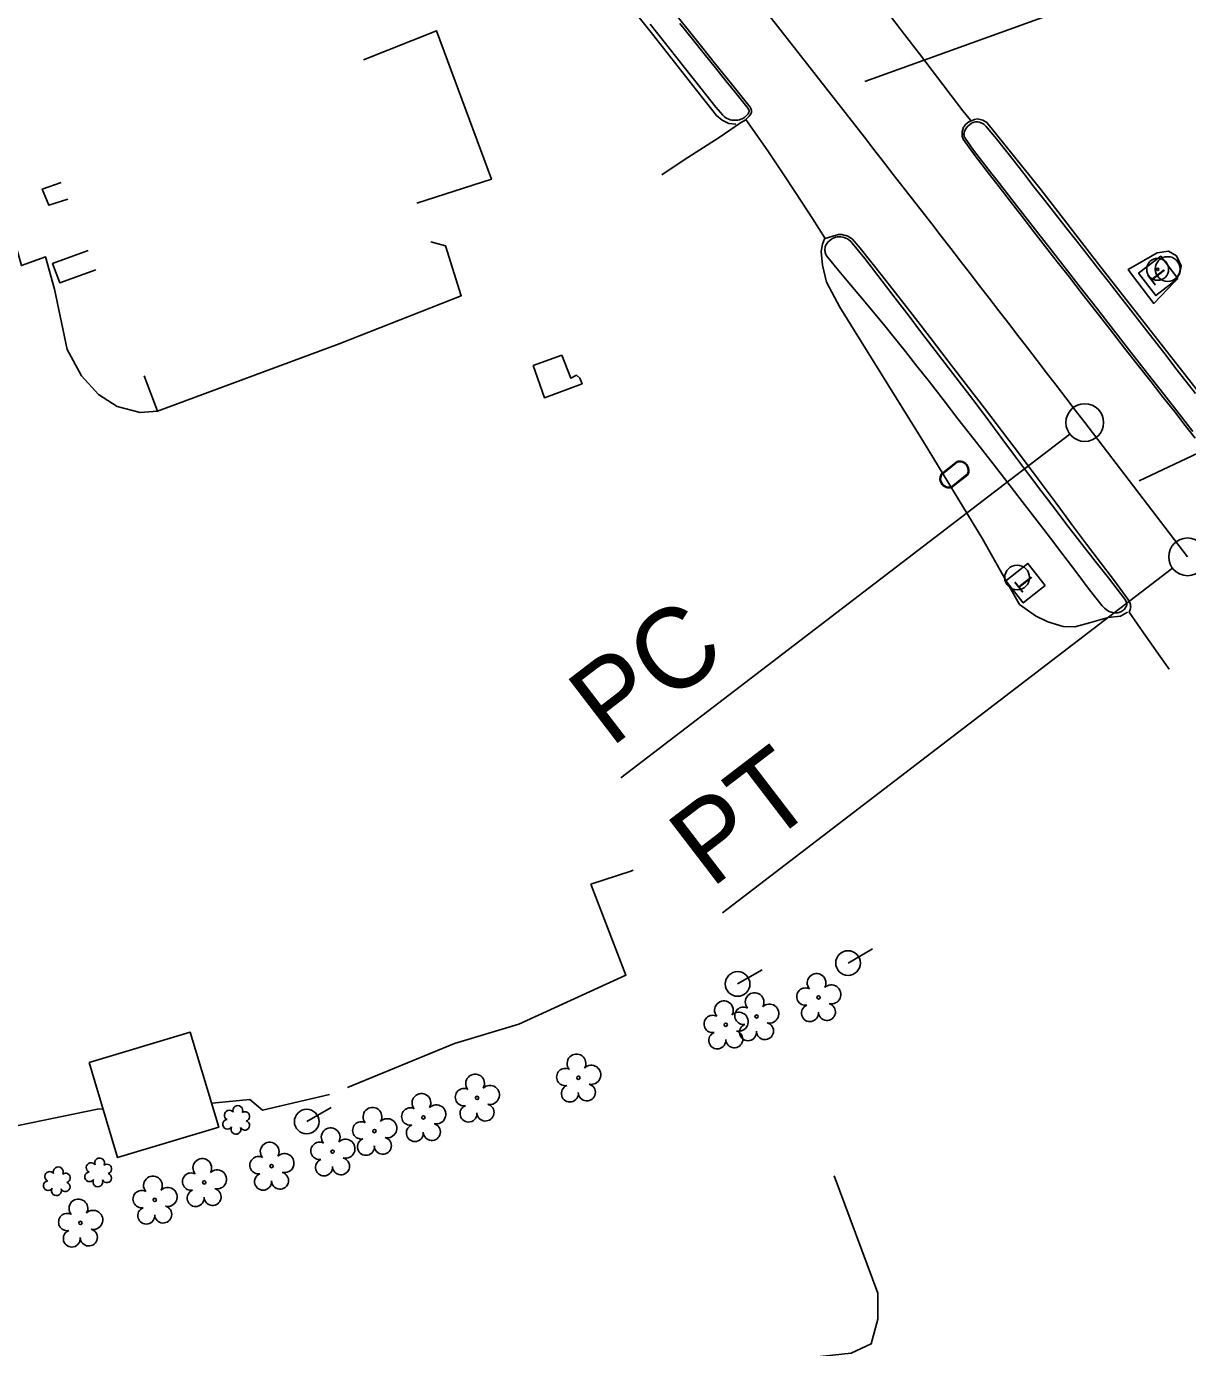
# Model space of a CAD drawing. Extents: x 471894 to 476235, y 503501 to 507878.
# Drawn here: x 473906 to 474137, y 505467.5 to 505730.3 of the extents above; entities that cross this region are included whole.
import ezdxf

# ---------------------------------------------------------------- set-up
doc = ezdxf.new("R2010")
doc.units = 0
for name, color, linetype in [('CTL Secondary Horizontal and Vertical Leader', 7, 'Continuous'), ('Exist Building Metal Canopy', 7, 'Continuous'), ('Exist Horizontal Alignment', 7, 'Continuous'), ('Exist Other Culture Area Outline', 7, 'Continuous'), ('Exist Roads Change in Surface', 7, 'Continuous'), ('Exist Roads Curbs', 7, 'Continuous'), ('Exist Roads EOP', 7, 'Continuous'), ('Exist Roads EOP Leader', 7, 'Continuous'), ('Exist Roads EOP Other', 7, 'Continuous'), ('Exist Roads Soil', 7, 'Continuous'), ('Exist Utilities Other Located Object CELL', 7, 'Continuous'), ('Exist Utilities Other Pole CELL', 7, 'Continuous'), ('Exist Utilities Power Pole CELL', 7, 'Continuous'), ('Exist Utilities Telephone Pedestal CELL', 7, 'Continuous'), ('Exist Utilities Water Meter CELL', 7, 'Continuous'), ('Exist Vegetation Shrub CELL', 7, 'Continuous'), ('Exist Vegetation Tree CELL', 7, 'Continuous')]:
    doc.layers.add(name, color=color, linetype=linetype)

msp = doc.modelspace()

# ---------------------------------------------------------------- linework, layer by layer
at = {"layer": 'CTL Secondary Horizontal and Vertical Leader'}
msp.add_lwpolyline([(474127.3, 505639.88), (474171.9, 505660.95), (474186.96, 505645.3)], dxfattribs=at)
at = {"layer": 'Exist Building Metal Canopy'}
msp.add_lwpolyline([(473918.51, 505524.23), (473938.62, 505530.24), (473944.28, 505511.32), (473924.17, 505505.31)], close=True, dxfattribs=at)
at = {"layer": 'Exist Horizontal Alignment'}
for p, q in [((474136.95, 505624.79), (474116.5, 505651.49)), ((474113.52, 505649.21), (474024.24, 505580.81)), ((474133.98, 505622.51), (474044.49, 505553.96))]:
    msp.add_line(p, q, dxfattribs=at)
for centre in [(474116.5, 505651.49), (474136.95, 505624.79)]:
    msp.add_circle(centre, 3.75, dxfattribs=at)
msp.add_arc((466857.69, 500090.63), 9144.05, 37.455153, 38.70549, dxfattribs=at)
at = {"layer": 'Exist Other Culture Area Outline'}
for points in [[(473914.26, 505695.9), (473910.49, 505694.73), (473909.19, 505697.94), (473912.94, 505699.23)], [(473919.84, 505681.86), (473912.65, 505679.27), (473911.23, 505683.13), (473918.32, 505685.69)]]:
    msp.add_lwpolyline(points, dxfattribs=at)
at = {"layer": 'Exist Roads Change in Surface'}
for points in [[(473973.08, 505723.67), (473987.58, 505729.42), (473998.5, 505699.88), (473983.65, 505695.11)], [(473986.47, 505687.46), (473989.35, 505686.67), (473992.52, 505676.71), (473968.23, 505667.13), (473932.1, 505653.75)], [(474012.51, 505664.89), (474014.33, 505660.3), (474015.42, 505660.91), (474016.09, 505660.3), (474016.55, 505659.2), (474009.04, 505656.44), (474006.83, 505662.83), (474012.51, 505664.89)]]:
    msp.add_lwpolyline(points, dxfattribs=at)
at = {"layer": 'Exist Roads Curbs'}
for points in [[(474030.1, 505730.71), (474033.4, 505726.59), (474036.84, 505722.18), (474040.14, 505717.98), (474043.13, 505714.23), (474044.52, 505712.61), (474044.81, 505712.35), (474045.11, 505712.13), (474045.41, 505711.95), (474045.71, 505711.81), (474046.02, 505711.7), (474046.36, 505711.64), (474046.73, 505711.61), (474047.11, 505711.62), (474047.49, 505711.65), (474047.83, 505711.72), (474048.13, 505711.81), (474048.39, 505711.92), (474048.82, 505712.19), (474049.18, 505712.47), (474049.33, 505712.62), (474049.46, 505712.77), (474049.57, 505712.92), (474049.66, 505713.07), (474049.73, 505713.22), (474049.77, 505713.35), (474049.78, 505713.46), (474049.76, 505713.56), (474049.71, 505713.66), (474049.54, 505713.93), (474046.91, 505717.26), (474045.14, 505719.48), (474043.06, 505722.07), (474040.85, 505724.83), (474038.48, 505727.77), (474035.98, 505730.89)], [(474138.52, 505657.25), (474136.61, 505659.73), (474134.65, 505662.27), (474132.68, 505664.82), (474130.76, 505667.31), (474128.87, 505669.74), (474127.02, 505672.12), (474125.15, 505674.51), (474123.21, 505676.98), (474121.2, 505679.54), (474119.13, 505682.18), (474117.02, 505684.86), (474114.91, 505687.55), (474112.79, 505690.24), (474110.68, 505692.93), (474108.57, 505695.63), (474106.46, 505698.32), (474104.36, 505701.02), (474102.26, 505703.72), (474098.95, 505707.95), (474096.86, 505710.47), (474096.65, 505710.67), (474096.48, 505710.81), (474096.33, 505710.91), (474096.15, 505711.01), (474095.72, 505711.19), (474095.48, 505711.26), (474095.24, 505711.3), (474095, 505711.31), (474094.77, 505711.29), (474094.54, 505711.24), (474094.32, 505711.18), (474094.11, 505711.09), (474093.92, 505710.98), (474093.57, 505710.73), (474093.27, 505710.46), (474093.12, 505710.31), (474092.99, 505710.13), (474092.74, 505709.72), (474092.63, 505709.5), (474092.55, 505709.3), (474092.51, 505709.11), (474092.49, 505708.94), (474092.49, 505708.78), (474092.52, 505708.61), (474092.55, 505708.44), (474092.6, 505708.27), (474092.71, 505708.04), (474094.37, 505705.68), (474097.31, 505701.88), (474099.53, 505699.04), (474102.03, 505695.85), (474104.58, 505692.58), (474107.18, 505689.25), (474109.84, 505685.85), (474112.62, 505682.27), (474115.62, 505678.43), (474118.82, 505674.32), (474122.23, 505669.94), (474125.68, 505665.51), (474129, 505661.25), (474132.2, 505657.14), (474135.27, 505653.2), (474137.99, 505649.7)]]:
    msp.add_lwpolyline(points, dxfattribs=at)
msp.add_lwpolyline([(474078.63, 505668.4), (474080.85, 505665.63), (474083.14, 505662.71), (474085.6, 505659.57), (474088.32, 505656.08), (474091.29, 505652.26), (474094.51, 505648.11), (474097.8, 505643.85), (474100.99, 505639.74), (474104.06, 505635.78), (474107.03, 505631.95), (474109.71, 505628.47), (474111.96, 505625.55), (474115.14, 505621.35), (474117.21, 505618.58), (474119.98, 505615.06), (474120.42, 505614.6), (474120.75, 505614.3), (474121.05, 505614.1), (474121.38, 505613.93), (474121.73, 505613.81), (474122.11, 505613.73), (474122.48, 505613.68), (474122.8, 505613.66), (474123.07, 505613.67), (474123.29, 505613.71), (474123.48, 505613.78), (474123.67, 505613.87), (474123.87, 505613.98), (474124.06, 505614.11), (474124.25, 505614.25), (474124.4, 505614.4), (474124.54, 505614.55), (474124.64, 505614.71), (474124.79, 505614.98), (474124.84, 505615.09), (474124.87, 505615.17), (474124.88, 505615.27), (474124.87, 505615.38), (474124.84, 505615.53), (474124.79, 505615.7), (474124.71, 505615.89), (474124.46, 505616.36), (474121.2, 505620.59), (474118.58, 505623.91), (474115.07, 505628.41), (474112.95, 505631.16), (474110.59, 505634.25), (474107.99, 505637.69), (474105.31, 505641.25), (474102.73, 505644.7), (474100.23, 505648.05), (474097.83, 505651.29), (474095.49, 505654.43), (474093.2, 505657.47), (474090.96, 505660.41), (474088.76, 505663.26), (474086.75, 505665.86), (474083.66, 505669.86), (474081.57, 505672.63), (474078.8, 505676.25), (474075.34, 505680.75), (474072.75, 505684.1), (474070.28, 505687.2), (474070, 505687.49), (474069.58, 505687.83), (474069.17, 505688.09), (474068.95, 505688.19), (474068.68, 505688.28), (474067.99, 505688.41), (474067.61, 505688.44), (474067.26, 505688.42), (474066.94, 505688.36), (474066.65, 505688.26), (474066.37, 505688.12), (474066.11, 505687.96), (474065.87, 505687.77), (474065.43, 505687.35), (474065.26, 505687.15), (474065.12, 505686.97), (474065.02, 505686.8), (474064.95, 505686.63), (474064.89, 505686.44), (474064.86, 505686.23), (474064.84, 505685.99), (474064.83, 505685.75), (474064.85, 505685.52), (474064.88, 505685.32), (474064.93, 505685.13), (474065, 505684.95), (474065.08, 505684.77), (474065.19, 505684.59), (474066.92, 505682.47), (474069.27, 505679.68), (474072.48, 505675.84), (474074.41, 505673.54), (474076.48, 505671.04)], close=True, dxfattribs=at)
at = {"layer": 'Exist Roads EOP'}
for points in [[(474133.27, 505602.46), (474131.51, 505604.96), (474128.67, 505609.03), (474125.37, 505613.75), (474125.56, 505614.34), (474125.62, 505614.57), (474125.64, 505614.77), (474125.63, 505614.95), (474125.62, 505615.12), (474125.58, 505615.3), (474125.54, 505615.49), (474125.45, 505615.7), (474125.08, 505616.37), (474122.43, 505620.02), (474119.19, 505624.25), (474116.88, 505627.31), (474114.08, 505631.05), (474110.79, 505635.46), (474107.25, 505640.21), (474103.7, 505644.94), (474100.13, 505649.66), (474096.55, 505654.36), (474092.95, 505659.05), (474089.36, 505663.73), (474085.75, 505668.39), (474082.15, 505673.05), (474078.86, 505677.29), (474076.21, 505680.69), (474074.19, 505683.25), (474071.86, 505686.16), (474070.25, 505688.01), (474070, 505688.2), (474069.71, 505688.38), (474069.36, 505688.54), (474068.98, 505688.68), (474068.57, 505688.8), (474068.19, 505688.87), (474067.84, 505688.89), (474067.5, 505688.88), (474067.09, 505688.8), (474064.86, 505688.13), (474062.36, 505692.05), (474059.11, 505697.08), (474056.52, 505700.98), (474053.46, 505705.54), (474050.51, 505709.8), (474049.11, 505711.76), (474049.77, 505712.46), (474050.12, 505712.91), (474050.25, 505713.23), (474050.24, 505713.57), (474050.19, 505713.76), (474050.09, 505713.98), (474049.95, 505714.22), (474046.24, 505718.88), (474042.82, 505723.13), (474040.58, 505725.93), (474038.16, 505728.97), (474035.74, 505731.99)], [(474077.22, 505733.16), (474080.64, 505728.7), (474083.62, 505724.81), (474086.16, 505721.49), (474088.26, 505718.74), (474089.96, 505716.52), (474092.28, 505713.5), (474093.76, 505711.63), (474093.63, 505711.4), (474093.44, 505711.31), (474093.16, 505711.1), (474092.71, 505710.68), (474092.51, 505710.41), (474092.41, 505710.23), (474092.25, 505709.79), (474092.15, 505709.4), (474092.11, 505709.07), (474092.11, 505708.74), (474092.15, 505708.4), (474092.19, 505708.23), (474092.25, 505708.06), (474092.33, 505707.88), (474094.71, 505704.57), (474097.56, 505700.82), (474099.46, 505698.35), (474101.67, 505695.5), (474104.04, 505692.45), (474106.39, 505689.43), (474108.73, 505686.43), (474111.05, 505683.45), (474113.45, 505680.39), (474116, 505677.12), (474118.7, 505673.66), (474121.55, 505669.99), (474124.41, 505666.32), (474127.13, 505662.85), (474129.7, 505659.57), (474132.13, 505656.49), (474134.4, 505653.6), (474136.5, 505650.9), (474138.44, 505648.4)]]:
    msp.add_lwpolyline(points, dxfattribs=at)
at = {"layer": 'Exist Roads EOP Leader'}
msp.add_lwpolyline([(474072.77, 505719.35), (474153.88, 505748.66), (474167.52, 505734.48)], dxfattribs=at)
at = {"layer": 'Exist Roads EOP Other'}
for points in [[(474049.08, 505711.69), (474048.03, 505711.11), (474043.83, 505708.18), (474036.87, 505703.72), (474032.43, 505700.8)], [(473830.85, 505668), (473842.28, 505672.38), (473841.63, 505675.2), (473869.94, 505687.11), (473900.68, 505697.81), (473905.05, 505682.72), (473909.85, 505684.44), (473911.64, 505678), (473914.16, 505666.01), (473917.02, 505660.82), (473920.35, 505657.09), (473924.09, 505654.72), (473928.68, 505653.47), (473932.1, 505653.75)], [(474125.02, 505613.8), (474123.59, 505612.99), (474123.59, 505612.99), (474121.14, 505612.69), (474117.47, 505611.67), (474114.56, 505610.87), (474112.21, 505610.96), (474109.19, 505611.86), (474106.68, 505613.03), (474103.52, 505615.31), (474096.18, 505628.35), (474084.47, 505647.68), (474067.79, 505674.48), (474065.12, 505679.41), (474064.33, 505682.77), (474064.11, 505685.49), (474064.33, 505686.99), (474064.78, 505688.06)], [(474125.77, 505681.04), (474130.23, 505675.18), (474134.38, 505679.47), (474135.42, 505681.19), (474135.7, 505682.64), (474134.73, 505684.68), (474133.13, 505685.6), (474130.88, 505685.28), (474125.14, 505681.97), (474125.77, 505681.04)], [(473932.1, 505653.75), (473929.44, 505660.77)], [(474026.73, 505562.44), (474026.24, 505562.28), (474018.29, 505559.65)], [(473969.9, 505519.21), (473991.18, 505527.97), (474003.94, 505531.85), (474025.26, 505541.55), (474018.29, 505559.65)], [(473942.84, 505516.13), (473943.67, 505516.17), (473950.48, 505516.88), (473952.97, 505514.76), (473966.28, 505517.88)], [(473763.15, 505485.69), (473771.07, 505486.27), (473794.8, 505487.94), (473819.12, 505491.87), (473845.47, 505498.9), (473872.14, 505505.17), (473900.15, 505510.82), (473920.17, 505514.94), (473921.27, 505515)]]:
    msp.add_lwpolyline(points, dxfattribs=at)
at = {"layer": 'Exist Roads Soil'}
for points in [[(474014.51, 505758.85), (474013.4, 505759.5), (474012.35, 505759.68), (474010.66, 505759.03), (474010.01, 505758.31), (474009.52, 505757.51), (474009.44, 505756.42), (474009.86, 505755.18), (474015.85, 505747.27), (474030.57, 505728.76), (474039.3, 505717.6), (474043.29, 505712.6), (474044.37, 505711.65), (474045.72, 505710.99), (474047.14, 505710.82)], [(474146.25, 505648.25), (474140.76, 505655.46), (474119.23, 505683), (474107.74, 505697.85), (474107.74, 505697.85), (474097.02, 505711.2), (474096.21, 505711.62), (474095.17, 505711.89), (474094.56, 505711.77), (474093.79, 505711.47)], [(473816.42, 505415.8), (473837.36, 505419.29), (473869.01, 505426.53), (473894.79, 505427.86), (473913.99, 505427.52), (473939.29, 505434.34), (473951.85, 505432.89), (473973.66, 505436.95), (474000.87, 505444.96), (474016.81, 505450.81), (474034.45, 505461.6), (474042.25, 505464.97), (474058.91, 505465.18), (474070.04, 505466.37), (474074.06, 505468.28), (474075.38, 505473.13), (474075.38, 505478.33), (474066.64, 505501.67)]]:
    msp.add_lwpolyline(points, dxfattribs=at)
at = {"layer": 'Exist Utilities Other Located Object CELL'}
for radius in [2.18, 0.24]:
    msp.add_circle((474131.01, 505681.98), radius, dxfattribs=at)
at = {"layer": 'Exist Utilities Other Pole CELL'}
for centre in [(474132.99, 505682.03), (474103.05, 505620.67)]:
    msp.add_circle(centre, 2.46, dxfattribs=at)
at = {"layer": 'Exist Utilities Power Pole CELL'}
for p, q in [((474069.43, 505543.99), (474074.31, 505546.8)), ((474047.47, 505539.83), (474052.35, 505542.64)), ((474069.43, 505543.99), (474069.43, 505543.99)), ((474047.47, 505539.83), (474047.47, 505539.83)), ((473961.78, 505512.46), (473966.65, 505515.27)), ((473961.78, 505512.46), (473961.78, 505512.46))]:
    msp.add_line(p, q, dxfattribs=at)
for centre in [(474069.43, 505543.99), (474047.47, 505539.83), (473961.78, 505512.46)]:
    msp.add_circle(centre, 2.45, dxfattribs=at)
at = {"layer": 'Exist Utilities Telephone Pedestal CELL'}
for p, q in [((474131.14, 505680.59), (474131.14, 505680.59)), ((474104.76, 505619.48), (474104.76, 505619.48))]:
    msp.add_line(p, q, dxfattribs=at)
for points in [[(474135.04, 505680.15), (474131.63, 505684.59), (474127.2, 505681.18), (474130.61, 505676.74), (474135.04, 505680.15)], [(474108.66, 505619.09), (474105.2, 505623.49), (474100.8, 505620.03), (474104.26, 505615.63), (474108.66, 505619.09)]]:
    msp.add_lwpolyline(points, dxfattribs=at)
at = {"layer": 'Exist Utilities Water Meter CELL'}
msp.add_line((474090.58, 505641.17), (474090.58, 505641.17), dxfattribs=at)
for points in [[(474087.93, 505641.24), (474091.12, 505643.77)], [(474088.02, 505641.13), (474091.21, 505643.66)], [(474093.15, 505641.21), (474089.94, 505638.66)], [(474093.24, 505641.1), (474090.02, 505638.56)]]:
    msp.add_lwpolyline(points, dxfattribs=at)
for centre, radius, start, end in [((474091.6, 505641.97), 1.86, 332.0613, 104.7213), ((474091.61, 505641.98), 1.73, 333.5401, 103.2858), ((474089.56, 505640.35), 1.86, 151.591, 284.3924), ((474089.57, 505640.36), 1.73, 153.7139, 282.1953)]:
    msp.add_arc(centre, radius, start, end, dxfattribs=at)
at = {"layer": 'Exist Vegetation Shrub CELL'}
for p, q in [((473947.84, 505512.62), (473947.84, 505512.62)), ((473912.15, 505500.41), (473912.15, 505500.41)), ((473920.38, 505502.18), (473920.38, 505502.18))]:
    msp.add_line(p, q, dxfattribs=at)
for centre, radius, start, end in [((473948.07, 505514.66), 0.99, 334.8391, 200.4717), ((473946.04, 505511.92), 0.955, 95.1099, 327.9534), ((473946.36, 505513.75), 0.968, 35.8908, 245.4216), ((473949.51, 505513.49), 0.929, 284.4567, 126.0861), ((473947.71, 505510.94), 0.984, 151.2797, 21.387), ((473949.48, 505511.69), 0.937, 204.9913, 73.4601), ((473920.61, 505504.22), 0.99, 334.8391, 200.4717), ((473910.66, 505501.54), 0.968, 35.8908, 245.4216), ((473912.37, 505502.45), 0.99, 334.8391, 200.4717), ((473918.58, 505501.47), 0.955, 95.1099, 327.9534), ((473918.9, 505503.3), 0.968, 35.8908, 245.4216), ((473922.05, 505503.04), 0.929, 284.4567, 126.0861), ((473910.35, 505499.7), 0.955, 95.1099, 327.9534), ((473913.78, 505499.48), 0.937, 204.9913, 73.4601), ((473913.82, 505501.28), 0.929, 284.4567, 126.0861), ((473920.25, 505500.49), 0.984, 151.2797, 21.387), ((473922.02, 505501.25), 0.937, 204.9913, 73.4601), ((473912.02, 505498.72), 0.984, 151.2797, 21.387)]:
    msp.add_arc(centre, radius, start, end, dxfattribs=at)
at = {"layer": 'Exist Vegetation Tree CELL'}
for p, q in [((474063.56, 505537.16), (474063.56, 505537.16)), ((474045.12, 505531.73), (474045.12, 505531.73)), ((474051.23, 505533.36), (474051.23, 505533.36)), ((474015.82, 505521.17), (474015.82, 505521.17)), ((473995.66, 505517.17), (473995.66, 505517.17)), ((473984.99, 505513.3), (473984.99, 505513.3)), ((473975.25, 505510.56), (473975.25, 505510.56)), ((473966.93, 505506.48), (473966.93, 505506.48)), ((473954.8, 505503.62), (473954.8, 505503.62)), ((473941.39, 505500.37), (473941.39, 505500.37)), ((473931.57, 505496.88), (473931.57, 505496.88)), ((473916.77, 505492.32), (473916.77, 505492.32))]:
    msp.add_line(p, q, dxfattribs=at)
for centre in [(474063.56, 505537.16), (474045.12, 505531.73), (474051.23, 505533.36), (474015.82, 505521.17), (473995.66, 505517.17), (473984.99, 505513.3), (473975.25, 505510.56), (473966.93, 505506.48), (473954.8, 505503.62), (473941.39, 505500.37), (473931.57, 505496.88), (473916.77, 505492.32)]:
    msp.add_circle(centre, 0.326, dxfattribs=at)
for centre, radius, start, end in [((474063.17, 505540.04), 1.86, 330.1651, 219.7134), ((474066.11, 505537.75), 1.9, 257.1011, 134.1999), ((474050.85, 505536.23), 1.86, 330.1651, 219.7134), ((474060.95, 505537.32), 1.73, 62.6636, 279.3457), ((474044.74, 505534.6), 1.86, 330.1651, 219.7134), ((474047.67, 505532.32), 1.9, 257.1011, 134.1999), ((474048.63, 505533.51), 1.73, 62.6636, 279.3457), ((474053.78, 505533.94), 1.9, 257.1011, 134.1999), ((474061.85, 505534.04), 1.69, 111.5671, 6.231), ((474065.23, 505534.27), 1.7, 181.2822, 74.56), ((474042.52, 505531.88), 1.73, 62.6636, 279.3457), ((474049.53, 505530.23), 1.69, 111.5671, 6.231), ((474052.91, 505530.46), 1.7, 181.2822, 74.56), ((474043.42, 505528.61), 1.69, 111.5671, 6.231), ((474046.8, 505528.83), 1.7, 181.2822, 74.56), ((474015.43, 505524.04), 1.86, 330.1651, 219.7134), ((474018.36, 505521.76), 1.9, 257.1011, 134.1999), ((473995.27, 505520.04), 1.86, 330.1651, 219.7134), ((474013.21, 505521.32), 1.73, 62.6636, 279.3457), ((473993.05, 505517.32), 1.73, 62.6636, 279.3457), ((473998.21, 505517.76), 1.9, 257.1011, 134.1999), ((474014.11, 505518.05), 1.69, 111.5671, 6.231), ((474017.49, 505518.27), 1.7, 181.2822, 74.56), ((473984.6, 505516.18), 1.86, 330.1651, 219.7134), ((473987.54, 505513.89), 1.9, 257.1011, 134.1999), ((473993.95, 505514.05), 1.69, 111.5671, 6.231), ((473997.33, 505514.27), 1.7, 181.2822, 74.56), ((473974.86, 505513.43), 1.86, 330.1651, 219.7134), ((473977.8, 505511.14), 1.9, 257.1011, 134.1999), ((473982.38, 505513.46), 1.73, 62.6636, 279.3457), ((473966.54, 505509.35), 1.86, 330.1651, 219.7134), ((473972.64, 505510.71), 1.73, 62.6636, 279.3457), ((473983.28, 505510.18), 1.69, 111.5671, 6.231), ((473986.66, 505510.4), 1.7, 181.2822, 74.56), ((473954.41, 505506.49), 1.86, 330.1651, 219.7134), ((473964.32, 505506.63), 1.73, 62.6636, 279.3457), ((473969.47, 505507.06), 1.9, 257.1011, 134.1999), ((473973.55, 505507.44), 1.69, 111.5671, 6.231), ((473976.92, 505507.66), 1.7, 181.2822, 74.56), ((473941.01, 505503.24), 1.86, 330.1651, 219.7134), ((473952.19, 505503.78), 1.73, 62.6636, 279.3457), ((473957.35, 505504.21), 1.9, 257.1011, 134.1999), ((473965.22, 505503.35), 1.69, 111.5671, 6.231), ((473968.6, 505503.58), 1.7, 181.2822, 74.56), ((473943.94, 505500.96), 1.9, 257.1011, 134.1999), ((473956.47, 505500.72), 1.7, 181.2822, 74.56), ((473931.19, 505499.76), 1.86, 330.1651, 219.7134), ((473938.79, 505500.52), 1.73, 62.6636, 279.3457), ((473953.09, 505500.5), 1.69, 111.5671, 6.231), ((473916.38, 505495.19), 1.86, 330.1651, 219.7134), ((473928.96, 505497.04), 1.73, 62.6636, 279.3457), ((473934.12, 505497.47), 1.9, 257.1011, 134.1999), ((473939.69, 505497.25), 1.69, 111.5671, 6.231), ((473943.06, 505497.47), 1.7, 181.2822, 74.56), ((473919.32, 505492.91), 1.9, 257.1011, 134.1999), ((473929.87, 505493.76), 1.69, 111.5671, 6.231), ((473933.24, 505493.98), 1.7, 181.2822, 74.56), ((473914.16, 505492.48), 1.73, 62.6636, 279.3457), ((473915.06, 505489.2), 1.69, 111.5671, 6.231), ((473918.44, 505489.42), 1.7, 181.2822, 74.56)]:
    msp.add_arc(centre, radius, start, end, dxfattribs=at)

# ---------------------------------------------------------------- texts
at = {"layer": 'Exist Horizontal Alignment'}
for s, p in [('PC', (474022.21, 505586.68)), ('PT', (474042.18, 505558.68))]:
    msp.add_text(s, height=16, rotation=37.4552, dxfattribs=at).set_placement(p)
at = {"layer": 'Exist Utilities Telephone Pedestal CELL'}
for rotation, p in [(127.5864, (474133.19, 505680.74)), (128.2098, (474106.8, 505619.66))]:
    msp.add_text('T', height=3.42, rotation=rotation, dxfattribs=at).set_placement(p)

doc.saveas('drawing.dxf')
